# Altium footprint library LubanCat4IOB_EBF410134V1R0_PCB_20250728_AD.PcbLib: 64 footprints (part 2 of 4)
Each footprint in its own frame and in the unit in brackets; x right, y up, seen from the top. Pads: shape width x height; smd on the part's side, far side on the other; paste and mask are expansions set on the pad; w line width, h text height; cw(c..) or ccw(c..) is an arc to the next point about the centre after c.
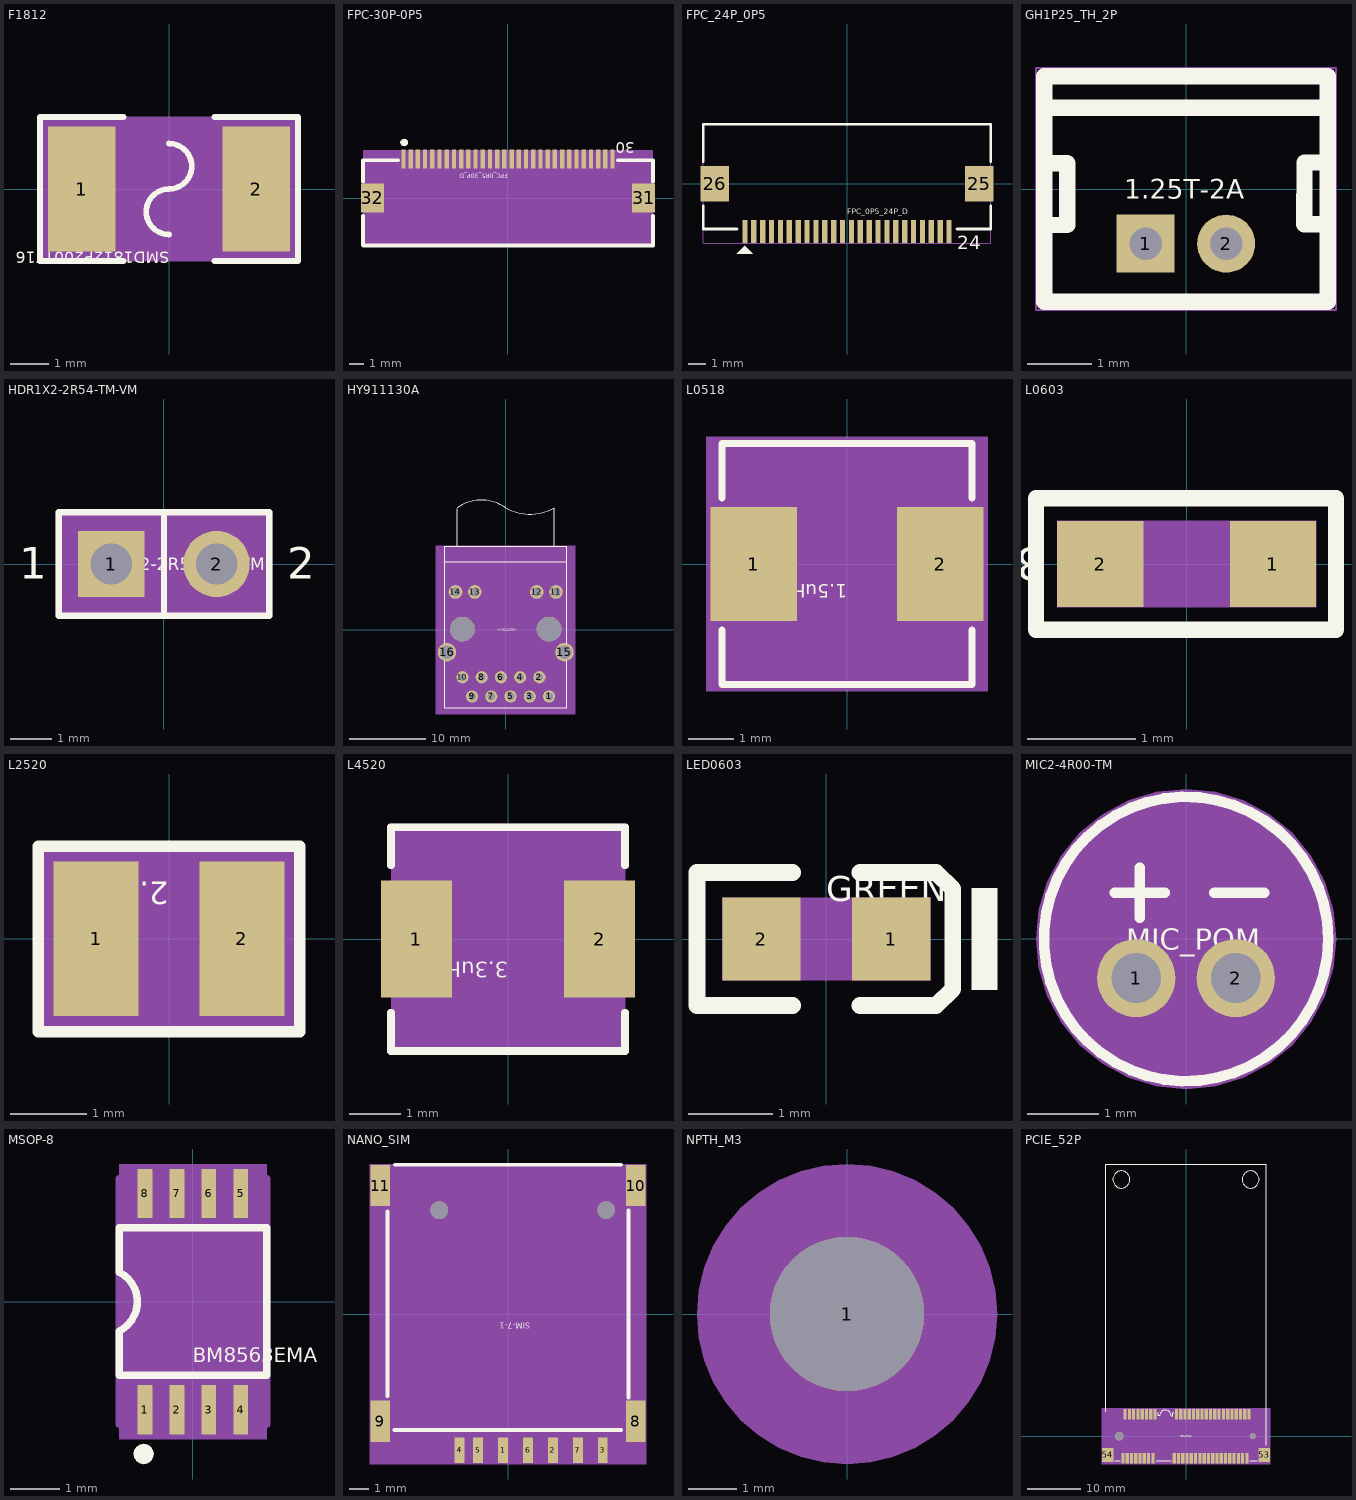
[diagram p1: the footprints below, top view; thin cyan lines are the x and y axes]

## F1812 [mm] "F1812"
pads (2):
  rect 1.78x3.3 smd: 1(-2.305,0) 2(2.305,0)
Top Overlay:
  lines w0.15: -1.2,-1.9 -3.4,-1.9 -3.4,1.9 -1.2,1.9 ; 0,-1.2 cw(c0,-0.6) 0,0 ccw(c0,0.6) 0,1.2 ; 1.2,-1.9 3.4,-1.9 3.4,1.9 1.2,1.9
  text "SMD1812P200TF16" at 0,-1.65 h0.3
Top 3D Body:
  region: -3.4,-1.9 3.4,-1.9 3.4,1.9 -3.4,1.9
Mechanical 17:
  text "2" at 2.305,-0.12 h0.3
  text "1" at -2.305,-0.12 h0.3
3D body: height 3.81, standoff 0, extent -3.4,-1.9 3.4,1.9

## FPC-30P-0P5 [mm] "FPC-30P-0P5"
pads (32):
  rect 0.3x1.3 smd: 1(-7.25,2.733) 2(-6.75,2.733) 3(-6.25,2.733) 4(-5.75,2.733) 5(-5.25,2.733) 6(-4.75,2.733) 7(-4.25,2.733) 8(-3.75,2.733) 9(-3.25,2.733) 10(-2.75,2.733) 11(-2.25,2.733) 12(-1.75,2.733) 13(-1.25,2.733) 14(-0.75,2.733) 15(-0.25,2.733) 16(0.25,2.733) 17(0.75,2.733) 18(1.25,2.733) 19(1.75,2.733) 20(2.25,2.733) 21(2.75,2.733) 22(3.25,2.733) 23(3.75,2.733) 24(4.25,2.733) 25(4.75,2.733) 26(5.25,2.733) 27(5.75,2.733) 28(6.25,2.733) 29(6.75,2.733) 30(7.25,2.733)
  rect 1.6x2 smd: 31(9.4,0.032) 32(-9.4,0.032)
Top Overlay:
  dashed: -7.2,3.628 -7.297,3.647 -7.38,3.702 -7.435,3.785 -7.455,3.882 -7.435,3.98 -7.417,4.008 -7.38,4.063 -7.297,4.118 -7.2,4.137 -7.102,4.118 -7.02,4.063 -6.983,4.008 -6.964,3.98 -6.945,3.882 -6.964,3.785 -7.02,3.702 -7.102,3.647
  lines w0.254: -10.05,-1.199 -10.05,-3.257 ; -10.05,1.164 -10.05,2.652 -7.631,2.652 ; 7.631,2.652 10.05,2.652 10.05,1.164 ; 10.05,-1.199 10.05,-3.268 -10.04,-3.268 -10.05,-3.257 ; -10.05,-3.257 -10.05,-3.257
  text "FPC_0R5_30P_D" at 0,1.71 h0.3
  text "30" at 8.794,3.891 h0.76
Top 3D Body:
  region: 10.052,-3.35 10.052,3.35 -10.052,3.35 -10.052,-3.35
Mechanical 17:
  text "5" at -5.25,2.813 h0.1
  text "4" at -5.75,2.813 h0.1
  text "1" at -7.25,2.813 h0.1
  text "2" at -6.75,2.813 h0.1
  text "3" at -6.25,2.813 h0.1
  text "14" at -0.75,2.893 h0.1
  text "12" at -1.75,2.893 h0.1
  text "11" at -2.25,2.893 h0.1
  text "15" at -0.25,2.893 h0.1
  text "13" at -1.25,2.893 h0.1
  text "9" at -3.25,2.813 h0.1
  text "10" at -2.75,2.893 h0.1
  text "23" at 3.75,2.893 h0.1
  text "24" at 4.25,2.893 h0.1
  text "26" at 5.25,2.893 h0.1
  text "27" at 5.75,2.893 h0.1
  text "20" at 2.25,2.893 h0.1
  text "21" at 2.75,2.893 h0.1
  text "17" at 0.75,2.893 h0.1
  text "18" at 1.25,2.893 h0.1
  text "29" at 6.75,2.893 h0.1
  text "30" at 7.25,2.893 h0.1
  text "28" at 6.25,2.893 h0.1
  text "25" at 4.75,2.893 h0.1
  text "22" at 3.25,2.893 h0.1
  text "16" at 0.25,2.893 h0.1
  text "19" at 1.75,2.893 h0.1
  text "31" at 8.89,0.112 h0.1
  text "8" at -3.75,2.813 h0.1
  text "7" at -4.25,2.813 h0.1
  text "6" at -4.75,2.813 h0.1
  text "32" at -10.16,0.112 h0.1
3D body: height 3.81, standoff 0, extent -10.052,-3.35 10.052,3.35

## FPC_24P_0P5 [mm] "FPC_24P_0P5"
pads (26):
  rect 0.3x1.3 smd: 1(-5.75,-2.701) 2(-5.25,-2.701) 3(-4.75,-2.701) 4(-4.25,-2.701) 5(-3.75,-2.701) 6(-3.25,-2.701) 7(-2.75,-2.701) 8(-2.25,-2.701) 9(-1.75,-2.701) 10(-1.25,-2.701) 11(-0.75,-2.701) 12(-0.25,-2.701) 13(0.25,-2.701) 14(0.75,-2.701) 15(1.25,-2.701) 16(1.75,-2.701) 17(2.25,-2.701) 18(2.75,-2.701) 19(3.25,-2.701) 20(3.75,-2.701) 21(4.25,-2.701) 22(4.75,-2.701) 23(5.25,-2.701) 24(5.75,-2.701)
  rect 1.6x2 smd: 25(7.45,0.001) 26(-7.45,0.001)
Top Overlay:
  dashed: -6.199,-3.95 -5.301,-3.95 -5.75,-3.501
  lines w0.15: -8.1,-1.25 -8.1,-2.55 -6.2,-2.55 ; -8.1,1.25 -8.1,3.35 8.1,3.35 8.1,1.25 ; 6.2,-2.55 8.1,-2.55 8.1,-1.25
  text "FPC_0P5_24P_D" at 0,-1.71 h0.3
  text "24" at 6.213,-3.682 h0.76
Top 3D Body:
  lines w0.025: -8.1,-3.35 -8.1,3.35 8.1,3.35 8.1,-3.35 -8.1,-3.35
Mechanical 17:
  text "3" at -4.75,-2.955 h0.64
  text "2" at -5.25,-2.955 h0.64
  text "1" at -5.75,-2.955 h0.64
  text "5" at -3.75,-2.955 h0.64
  text "6" at -3.25,-2.955 h0.64
  text "13" at 0.25,-3.209 h0.64
  text "14" at 0.75,-3.209 h0.64
  text "16" at 1.75,-3.209 h0.64
  text "17" at 2.25,-3.209 h0.64
  text "19" at 3.25,-3.209 h0.64
  text "20" at 3.75,-3.209 h0.64
  text "22" at 4.75,-3.209 h0.64
  text "15" at 1.25,-3.209 h0.64
  text "10" at -1.25,-3.209 h0.64
  text "11" at -0.75,-3.209 h0.64
  text "8" at -2.25,-2.955 h0.64
  text "7" at -2.75,-2.955 h0.64
  text "9" at -1.75,-2.955 h0.64
  text "12" at -0.25,-3.209 h0.64
  text "4" at -4.25,-2.955 h0.64
  text "26" at -7.45,-0.507 h0.64
  text "18" at 2.75,-3.209 h0.64
  text "21" at 4.25,-3.209 h0.64
  text "23" at 5.25,-3.209 h0.64
  text "24" at 5.75,-3.209 h0.64
  text "25" at 7.45,-0.507 h0.64

## GH1P25_TH_2P [mm] "GH1P25_TH_2P"
pads (2):
  rect 0.9x0.9 / inner round 1.524 / far side rect 0.9x0.9 hole 0.5: 1(-0.626,-0.849)
  round 0.9 hole 0.5: 2(0.624,-0.849)
Top Overlay:
  lines w0.254: -2.202,0.401 -1.841,0.401 -1.841,-0.559 -2.161,-0.559 ; -2.201,1.262 2.199,1.262 ; 2.159,-0.549 1.839,-0.548 1.839,0.411 2.2,0.411 ; 2.199,-1.749 -2.201,-1.749 -2.201,1.751 2.199,1.751 ; 2.202,-1.751 2.202,1.749
  text "1.25T-2A" at -0.96,-0.15 h0.3
Bottom Overlay:
  lines w0.2: -0.001,-1.549 -0.001,-0.149
  lines w0.3: -1.401,-1.549 -1.401,-0.149 1.399,-0.149 1.399,-1.549 -1.101,-1.549 -1.401,-1.549
Top 3D Body:
  lines w0.025: -2.329,-1.878 2.329,-1.878 2.329,1.878 -2.329,1.878 -2.329,-1.878
Mechanical 17:
  text "1" at -0.88,-0.849 h0.64
  text "2" at 0.37,-0.849 h0.64

## HDR1X2-2R54-TM-VM [mm] "HDR1X2-2R54-TM-VM"
pads (2):
  rect 1.6x1.6 / inner round 1.524 / far side rect 1.6x1.6 hole 1: 1(-1.27,0)
  round 1.6 / inner round 1.524 / far side round 1.6 hole 1: 2(1.27,0)
Top Overlay:
  lines w0.15: 0,-1.25 0,1.25 ; -2.54,-1.25 2.54,-1.25 2.54,1.25 -2.54,1.25 -2.54,-1.25
  text "HDR1X2-2R54-TM-VM" at -2.04,-0.15 h0.3
  text "1" at -3.497,-0.351 h0.76
  text "2" at 2.98,-0.351 h0.76
Bottom Overlay:
  lines w0.5: 0,-0.55 0,0.55
Top 3D Body:
  region: -2.54,1.25 -2.54,-1.25 2.54,-1.25 2.54,1.25
Mechanical 17:
  text "2" at 1.016,0 h0.64
  text "1" at -1.524,0 h0.64
Top Assembly:
  lines w0.15: -2.54,-1.25 2.54,-1.25 2.54,1.25 -2.54,1.25 -2.54,-1.25
3D body: height 3.81, standoff 0, extent -2.54,-1.25 2.54,1.25

## HY911130A [mm] "HY911130A"
pads (18):
  round 1.6 / inner round 1.524 / far side round 1.6 hole 1: 1(5.72,-8.79) 2(4.45,-6.25) 3(3.18,-8.79) 4(1.91,-6.25) 5(0.64,-8.79) 6(-0.63,-6.25) 7(-1.9,-8.79) 8(-3.17,-6.25) 9(-4.44,-8.79)
  round 1.6 hole 1: 10(-5.71,-6.25)
  round 1.8 / inner round 1.524 / far side round 1.8 hole 1.2: 11(6.625,5) 12(4.085,5) 13(-4.085,5) 14(-6.625,5)
  round 2.43 / inner round 1.524 / far side round 2.43 hole 1.83: 15(7.745,-2.95) 16(-7.745,-2.95)
  round 3.25 hole 3.25 unplated: ""(-5.715,0.1) ""(5.715,0.1)
Top Overlay:
  lines w0.15: -6.4,16 -6.4,11 6.4,11 6.4,16 ; -6.4,16.1 cw(c-3.2,11.5) 0,16.1 ccw(c3.2,21.875) 6.4,16.1 ; -8.02,11 -8.02,9 8.02,9 ; -8.02,11 -8.02,-10.3 8.02,-10.3 8.02,9 ; -8.02,11 8.02,11 8.02,9
  text "HY911130A" at -1.08,-0.15 h0.3
Bottom Overlay:
  drawing of 17 lines, arcs and shapes, not listed
Top 3D Body:
  region: -9.2,11.1 -9.2,-11.1 9.2,-11.1 9.2,11.1
Mechanical 17:
  text "15" at 6.932,-2.95 h1.02
  text "16" at -8.558,-2.95 h1.02
  text "12" at 3.272,5 h1.02
  text "11" at 5.812,5 h1.02
  text "14" at -7.438,5 h1.02
  text "1" at 5.314,-8.79 h1.02
  text "13" at -4.898,5 h1.02
  text "9" at -4.846,-8.79 h1.02
  text "8" at -3.576,-6.25 h1.02
  text "6" at -1.036,-6.25 h1.02
  text "5" at 0.234,-8.79 h1.02
  text "7" at -2.306,-8.79 h1.02
  text "4" at 1.504,-6.25 h1.02
  text "3" at 2.774,-8.79 h1.02
  text "2" at 4.044,-6.25 h1.02
  text "10" at -6.523,-6.25 h1.02
3D body: height 3.81, standoff 0, extent -9.2,-11.1 9.2,11.1

## L0518 [mm] "L0518"
pads (2):
  rect 1.9x2.5 smd: 1(-2.05,0) 2(2.05,0)
Top Overlay:
  lines w0.15: -2.75,-1.45 -2.75,-2.65 2.75,-2.65 2.75,-1.45 ; -2.75,1.45 -2.75,2.65 2.75,2.65 2.75,1.45
  text "1.5uH" at 0,-0.45 h0.3
Top 3D Body:
  region: -3.1,2.8 -3.1,-2.8 3.1,-2.8 3.1,2.8
Mechanical 17:
  text "1" at -1.9,-0.708 h0.64
  text "2" at 2.2,-0.808 h0.64
Top Assembly:
  lines w0.15: -2.75,-1.45 -2.75,-2.65 2.75,-2.65 2.75,-1.45 ; -2.75,1.45 -2.75,2.65 2.75,2.65 2.75,1.45
3D body: height 3.81, standoff 0, extent -3.1,-2.8 3.1,2.8

## L0603 [mil] "L0603"
pads (2):
  rect 31.5x31.5 smd: 1(31.5,0) 2(-31.5,0)
Top Overlay:
  lines w6: -55,-24 54.5,-24 54.5,24 -55,24 -55,-24
  text "330R 100MHz" at -51.97,5.91 h11.81
Top 3D Body:
  region: 47.24,15.75 47.24,-15.75 -47.24,-15.75 -47.24,15.75
Mechanical 17:
  text "1" at 13.5,0 h45
  text "2" at -49.5,0 h45
3D body: height 150, standoff 0, extent -47.24,-15.75 47.24,15.75

## L2520 [mil] "L2520"
pads (2):
  rect 44x80 smd: 1(-37.75,0) 2(37.75,0)
Top Overlay:
  lines w6: -67.68,-48.15 -67.68,47.92 67.67,47.92 67.67,-48.15 -67.67,-48.15 -67.68,-48.15
  text "2.2uH" at -0.01,29.53 h11.81
Top 3D Body:
  region: -65,-45 65,-45 65,45 -65,45
Mechanical 17:
  text "1" at -37.75,4.72 h11.81
  text "2" at 37.75,4.72 h11.81
3D body: height 150, standoff 0, extent -65,-45 65,45

## L4520 [mm] "L4520"
pads (2):
  rect 1.4x2.3 smd: 1(-1.803,-0.002) 2(1.798,-0.002)
Top Overlay:
  lines w0.15: -2.303,-1.452 -2.303,-2.202 2.297,-2.202 2.297,-1.452 ; -2.303,1.448 -2.303,2.198 2.297,2.198 2.297,1.448
  text "3.3uH" at 0,-0.45 h0.3
Top 3D Body:
  region: -2.303,-2.202 2.302,-2.202 2.302,2.203 -2.303,2.203
Mechanical 17:
  text "1" at -1.803,-0.256 h0.64
  text "2" at 1.798,-0.256 h0.64
Top Assembly:
  lines w0.15: -2.303,-1.452 -2.303,-2.202 2.297,-2.202 2.297,-1.452 ; -2.303,1.448 -2.303,2.198 2.297,2.198 2.297,1.448
3D body: height 3.81, standoff 0, extent -2.303,-2.202 2.302,2.203

## LED0603 [mm] "LED0603"
pads (2):
  rect 0.93x0.98 smd: 1(0.77,0) 2(-0.77,0)
Top Overlay:
  dashed: 1.725,-0.6 2.025,-0.6 2.025,0.6 1.725,0.6
  lines w0.2: -0.4,-0.79 -1.535,-0.79 -1.535,0.79 -0.4,0.79 ; 0.4,-0.79 1.3,-0.79 1.5,-0.597 1.5,0.597 1.3,0.79 0.4,0.79
  text "GREEN" at 0,0.45 h0.3
Top 3D Body:
  region: -1.235,-0.49 1.235,-0.49 1.235,0.49 -1.235,0.49
Mechanical 17:
  text "2" at -0.77,0.254 h0.64
  text "1" at 0.77,0.254 h0.64
3D body: height 3.81, standoff 0, extent -1.235,-0.49 1.235,0.49

## MIC2-4R00-TM [mm] "MIC2-4R00-TM"
pads (2):
  round 1.1 / inner round 1.524 / far side round 1.1 hole 0.7: 1(-0.7,-0.55) 2(0.7,-0.55)
Top Overlay:
  lines w0.15: -1,0.65 -0.3,0.65 ; -0.65,0.3 -0.65,1 ; 0.4,0.65 1.1,0.65 ; 2,0 ccw(c0,0) 2,0
  text "MIC_POM" at -0.84,-0.15 h0.3
Top 3D Body:
  region: 2.11,0 2.07,0.412 1.95,0.808 1.755,1.172 1.492,1.492 1.172,1.755 0.808,1.95 0.412,2.07 0,2.11 -0.412,2.07 -0.808,1.95 -1.051,1.82 -1.172,1.755 -1.492,1.492 -1.755,1.172 -1.95,0.808 -2.07,0.412 -2.11,0 -2.07,-0.412 -1.95,-0.808 -1.755,-1.172 -1.492,-1.492 -1.172,-1.755 -1.051,-1.82 -0.808,-1.95 -0.412,-2.07 0,-2.11 0.412,-2.07 0.808,-1.95 1.172,-1.755 1.492,-1.492 1.755,-1.172 1.95,-0.808 2.07,-0.412
Mechanical 17:
  text "2" at 0.446,-0.55 h0.64
  text "1" at -0.954,-0.55 h0.64
Top Assembly:
  lines w0.15: 2,0 ccw(c0,0) 2,0
3D body: height 3.81, standoff 0, extent -2.11,-2.11 2.11,2.11

## MSOP-8 [mm] "MSOP-8"
pads (8):
  rect 0.3x1 smd: 1(-0.975,-2.2) 2(-0.325,-2.2) 3(0.325,-2.2) 4(0.975,-2.2) 5(0.975,2.2) 6(0.325,2.2) 7(-0.325,2.2) 8(-0.975,2.2)
Top Overlay:
  dashed: -1,-2.896 -0.922,-2.912 -0.856,-2.956 -0.812,-3.022 -0.796,-3.1 -0.812,-3.178 -0.826,-3.2 -0.856,-3.244 -0.922,-3.288 -1,-3.304 -1.078,-3.288 -1.144,-3.244 -1.174,-3.2 -1.188,-3.178 -1.204,-3.1 -1.188,-3.022 -1.144,-2.956 -1.078,-2.912
  lines w0.15: -1.5,-1.5 1.5,-1.5 1.5,1.5 -1.5,1.5 -1.5,0.6 cw(c-1.8,0) -1.5,-0.6 -1.5,-1.5
  text "BM8563EMA" at 0,-1.23 h0.3
Top 3D Body:
  region: -1.5,2.8 -1.5,-2.8 1.5,-2.8 1.5,2.8
Mechanical 17:
  text "5" at 1.105,1.86 h0.3
  text "2" at -0.195,-2.54 h0.3
  text "6" at 0.455,1.86 h0.3
  text "7" at -0.195,1.86 h0.3
  text "8" at -0.845,1.86 h0.3
  text "3" at 0.455,-2.54 h0.3
  text "1" at -0.845,-2.54 h0.3
  text "4" at 1.105,-2.54 h0.3
Top Assembly:
  lines w0.15: -1.5,-2.5 1.5,-2.5 1.5,2.5 -1.5,2.5 -1.5,-2.5 ; -1.5,-1.5 1.5,-1.5 1.5,1.5 -1.5,1.5 -1.5,-1.5
3D body: height 3.81, standoff 0, extent -1.5,-2.8 1.5,2.8

## NANO_SIM [mm] "NANO_SIM"
pads (13):
  rect 0.5x1.3 smd: 1(-0.25,-6.94) 2(2.29,-6.94) 3(4.83,-6.94) 4(-2.47,-6.94) 5(-1.52,-6.94) 6(1.02,-6.94) 7(3.56,-6.94)
  rect 1x2.1 smd: 8(6.5,-5.46) 9(-6.5,-5.46) 10(6.5,6.54) 11(-6.5,6.54)
  round 0.9 hole 0.9 unplated: ""(-3.5,5.29) ""(5,5.29)
Top Overlay:
  lines w0.2: -6.145,-4.189 -6.145,5.215 ; -5.784,-5.9 5.756,-5.9 ; -5.749,7.6 0,7.6 5.749,7.6 ; 6.145,-4.247 6.145,5.268
  text "SIM-7-1" at 1.125,-0.435 h0.3
Top 3D Body:
  region: 7.05,7.64 7.05,-7.64 -7.05,-7.64 -7.05,7.64
Mechanical 17:
  text "1" at -0.37,-6.94 h0.3
  text "3" at 4.71,-6.94 h0.3
  text "2" at 2.17,-6.94 h0.3
  text "7" at 3.44,-6.94 h0.3
  text "5" at -1.64,-6.94 h0.3
  text "8" at 6.38,-5.46 h0.3
  text "9" at -6.62,-5.46 h0.3
  text "10" at 6.26,6.54 h0.3
  text "11" at -6.74,6.54 h0.3
  text "6" at 0.9,-6.94 h0.3
  text "4" at -2.59,-6.94 h0.3
3D body: height 3.81, standoff 0, extent -7.05,-7.64 7.05,7.64

## NPTH_M3 [mm] "NPTH_M3"
pads (1):
  round 3.2 / inner round 1.524 / far side round 3.2 hole 3.2 unplated: 1(0,0)
Top Overlay:
  text "NPTH_M3" at -0.84,-0.15 h0.3
Top 3D Body:
  region: 3.11,0 3.071,0.486 2.957,0.961 2.771,1.412 2.516,1.828 2.199,2.199 1.828,2.516 1.412,2.771 0.961,2.957 0.486,3.071 0,3.11 -0.486,3.071 -0.961,2.957 -1.412,2.771 -1.551,2.686 -1.828,2.516 -2.199,2.199 -2.516,1.828 -2.771,1.412 -2.957,0.961 -3.071,0.486 -3.11,0 -3.071,-0.486 -2.957,-0.961 -2.771,-1.412 -2.516,-1.828 -2.199,-2.199 -1.828,-2.516 -1.551,-2.686 -1.412,-2.771 -0.961,-2.957 -0.486,-3.071 0,-3.11 0.486,-3.071 0.961,-2.957 1.412,-2.771 1.828,-2.516 2.199,-2.199 2.516,-1.828 2.771,-1.412 2.957,-0.961 3.071,-0.486
Mechanical 17:
  text "1" at -0.254,0 h0.64
3D body: height 3.81, standoff 0, extent -3.11,-3.11 3.11,3.11

## PCIE_52P [mm] "PCIE_52P"
pads (56):
  rect 0.6x2 smd: 1(-11.8,-4.1) 2(-11.4,4.1) 3(-11,-4.1) 4(-10.6,4.1) 5(-10.2,-4.1) 6(-9.8,4.1) 7(-9.4,-4.1) 8(-9,4.1) 9(-8.6,-4.1) 10(-8.2,4.1) 11(-7.8,-4.1) 12(-7.4,4.1) 13(-7,-4.1) 14(-6.6,4.1) 15(-6.2,-4.1) 16(-5.8,4.1) 17(-2.2,-4.1) 18(-1.8,4.1) 19(-1.4,-4.1) 20(-1,4.1) 21(-0.6,-4.1) 22(-0.2,4.1) 23(0.2,-4.1) 24(0.6,4.1) 25(1,-4.1) 26(1.4,4.1) 27(1.8,-4.1) 28(2.2,4.1) 29(2.6,-4.1) 30(3,4.1) 31(3.4,-4.1) 32(3.8,4.1) 33(4.2,-4.1) 34(4.6,4.1) 35(5,-4.1) 36(5.4,4.1) 37(5.8,-4.1) 38(6.2,4.1) 39(6.6,-4.1) 40(7,4.1) 41(7.4,-4.1) 42(7.8,4.1) 43(8.2,-4.1) 44(8.6,4.1) 45(9,-4.1) 46(9.4,4.1) 47(9.8,-4.1) 48(10.2,4.1) 49(10.6,-4.1) 50(11,4.1) 51(11.4,-4.1) 52(11.8,4.1)
  rect 2.15x2.6 smd: 53(14.65,-3.5) 54(-14.65,-3.5)
  round 1.6 hole 1.6 unplated: ""(-12.5,0)
  round 1.1 hole 1.1 unplated: ""(12.5,0)
Top Overlay:
  lines w0.2: -15,4.6 -15,50.948 15,50.948 15,4.6 ; -13.3,-4.6 -12.3,-4.6 ; -5.6,-4.6 -2.8,-4.6 ; -5.325,4.387 -5.165,4.387 -5.165,3.883 -4.887,3.883 cw(c-3.843,3.859) -2.8,3.859 -2.8,3.847 -2.474,3.847 -2.474,4.381 -2.29,4.381 ; 11.9,-4.6 13.3,-4.6 ; 15,-1.7 15,4.6 ; 15,4.6 15,4.6 ; -13.7,48.049 ccw(c-12.1,48.049) -13.7,48.049 ; 10.5,48.049 ccw(c12.1,48.049) 10.5,48.049
  text "MINI-PCIE" at 1.08,0.15 h0.3
Top 3D Body:
  region: -15.8,-5.2 -15.8,5.2 15.8,5.2 15.8,-5.2
Mechanical 17:
  text "42" at 8.28,4.1 h0.3
  text "3" at -10.76,-4.1 h0.3
  text "6" at -9.56,4.1 h0.3
  text "48" at 10.68,4.1 h0.3
  text "45" at 9.48,-4.1 h0.3
  text "47" at 10.28,-4.1 h0.3
  text "49" at 11.08,-4.1 h0.3
  text "51" at 11.88,-4.1 h0.3
  text "17" at -1.72,-4.1 h0.3
  text "16" at -5.32,4.1 h0.3
  text "5" at -9.96,-4.1 h0.3
  text "28" at 2.68,4.1 h0.3
  text "30" at 3.48,4.1 h0.3
  text "46" at 9.88,4.1 h0.3
  text "44" at 9.08,4.1 h0.3
  text "19" at -0.92,-4.1 h0.3
  text "32" at 4.28,4.1 h0.3
  text "2" at -11.16,4.1 h0.3
  text "39" at 7.08,-4.1 h0.3
  text "24" at 1.08,4.1 h0.3
  text "52" at 12.28,4.1 h0.3
  text "41" at 7.88,-4.1 h0.3
  text "8" at -8.76,4.1 h0.3
  text "38" at 6.679,4.1 h0.3
  text "36" at 5.88,4.1 h0.3
  text "12" at -6.92,4.1 h0.3
  text "20" at -0.52,4.1 h0.3
  text "31" at 3.88,-4.1 h0.3
  text "7" at -9.16,-4.1 h0.3
  text "1" at -11.56,-4.1 h0.3
  text "33" at 4.68,-4.1 h0.3
  text "10" at -7.72,4.1 h0.3
  text "22" at 0.28,4.1 h0.3
  text "14" at -6.121,4.1 h0.3
  text "23" at 0.68,-4.1 h0.3
  text "25" at 1.48,-4.1 h0.3
  text "11" at -7.32,-4.1 h0.3
  text "13" at -6.521,-4.1 h0.3
  text "9" at -8.36,-4.1 h0.3
  text "43" at 8.68,-4.1 h0.3
  text "53" at 15.13,-3.5 h0.3
  text "4" at -10.36,4.1 h0.3
  text "26" at 1.88,4.1 h0.3
  text "18" at -1.32,4.1 h0.3
  text "50" at 11.48,4.1 h0.3
  text "54" at -14.17,-3.5 h0.3
  text "34" at 5.08,4.1 h0.3
  text "40" at 7.48,4.1 h0.3
  text "37" at 6.279,-4.1 h0.3
  text "35" at 5.48,-4.1 h0.3
  text "29" at 3.08,-4.1 h0.3
  text "27" at 2.28,-4.1 h0.3
  text "21" at -0.12,-4.1 h0.3
  text "15" at -5.72,-4.1 h0.3
Top Assembly:
  dashed: -15.8,5.2 -15.8,-5.2 15.8,-5.2 15.8,5.2
3D body: height 3.81, standoff 0, extent -15.8,-5.2 15.8,5.2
